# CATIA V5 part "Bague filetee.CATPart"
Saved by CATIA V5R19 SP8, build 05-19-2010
Part number: Bague filetee
Revision: ANY
Definition: UNKNOWN
Nomenclature: Bague filetée
Source: Unknown
Bounding box of the stored display mesh (mm): x -8.5 to 8.5, y -8.49 to 8.49, z 0 to 8
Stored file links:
  D:\Documents\1_Travail\1 - ac-limoges.fr\ac-limoges.fr\Emmanuel Maynard - STI2D_Turgot\2 -2I2D\3_SEQUENCE_Serre_Connectée\Dossier technique_SERRE\Maquettes_CATIA\Vérin_Thermodynamique\Bague filetee.CATPart
  D:\Documents\1_Travail\1 - ac-limoges.fr\ac-limoges.fr\Emmanuel Maynard - STI2D_Turgot\2 -2I2D\3_SEQUENCE_Serre_Connectée\Dossier technique_SERRE\Maquettes_CATIA\Vérin_Thermodynamique\Verin thermodynamique.CATProduct
  D:\Documents\1_Travail\1 - ac-limoges.fr\ac-limoges.fr\Emmanuel Maynard - STI2D_Turgot\2 -2I2D\3_SEQUENCE_Serre_Connectée\Dossier technique_SERRE\Maquettes_CATIA\Vérin_Thermodynamique\Tige_de_verin.CATPart
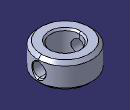
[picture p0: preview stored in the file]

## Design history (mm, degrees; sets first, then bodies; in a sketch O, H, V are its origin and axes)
Body1 "NONE" (main body)
  Solid1: solid without history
